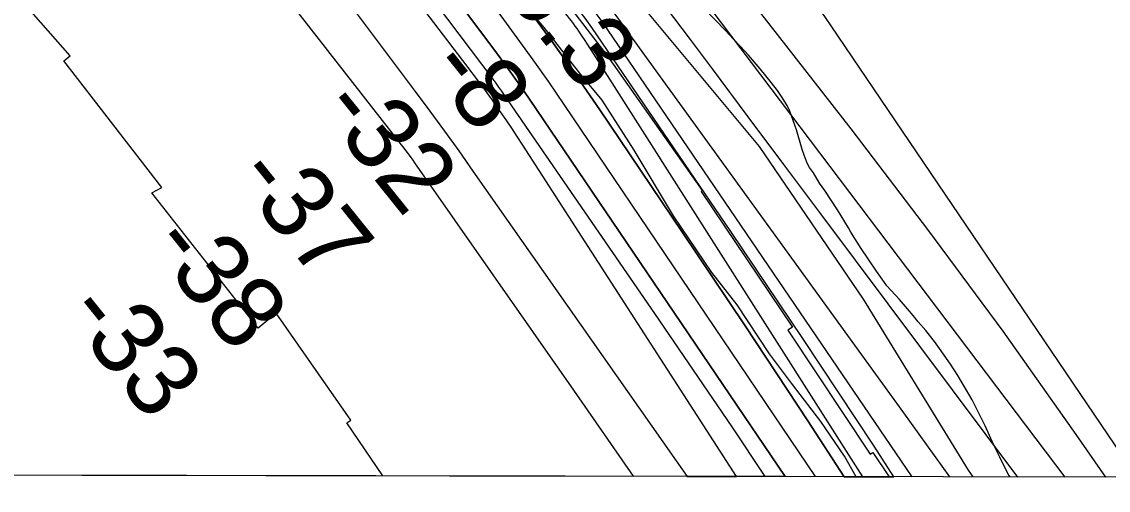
# Model space of a CAD drawing. Extents: x 3192986 to 3230865, y 867483 to 892886.
# Drawn here: x 3221191 to 3222187, y 872862 to 873292 of the extents above; entities that cross this region are included whole.
import ezdxf

# ---------------------------------------------------------------- set-up
doc = ezdxf.new("R2010")
doc.units = 0
for name, color, linetype in [('V-GRID-FRAM', 7, 'Continuous'), ('V-RIVR-EDGE', 7, 'Continuous'), ('V-RIVR-RANG', 7, 'Continuous'), ('V-RRAP-FSHR', 7, 'Continuous'), ('V-RRAP-RVMT', 7, 'Continuous'), ('V-SITE-VEGE', 7, 'Continuous'), ('V-TOPO-DPTH', 7, 'Continuous'), ('V-TOPO-MAJR', 7, 'Continuous'), ('V-TOPO-MINR', 7, 'Continuous'), ('V-TOPO-WATR', 7, 'Continuous')]:
    doc.layers.add(name, color=color, linetype=linetype)

msp = doc.modelspace()

# ---------------------------------------------------------------- linework, layer by layer
at = {"layer": 'V-GRID-FRAM'}
msp.add_lwpolyline([(3197228.98, 891108.84), (3228580.58, 891049.56), (3228554.13, 872861.57), (3197186.66, 872920.88)], dxfattribs=at)
at = {"layer": 'V-RIVR-EDGE'}
msp.add_lwpolyline([(3221955.99, 872874.04), (3221945.27, 872892.84), (3221923.62, 872924.62), (3221896.75, 872959.9), (3221876.39, 872986.9), (3221846.94, 873031.74), (3221823.54, 873061.36), (3221788.46, 873113.61), (3221752.53, 873173.68), (3221723.09, 873219.83), (3221703.59, 873243.35), (3221669.79, 873286.47), (3221630.35, 873332.64)], dxfattribs=at)
at = {"layer": 'V-RRAP-FSHR'}
msp.add_lwpolyline([(3221070.16, 874134.12), (3221108.41, 874083.35), (3221205.98, 873971.1), (3221288.17, 873882.52), (3221420.05, 873732.91), (3221529.87, 873601.58), (3221600.18, 873512.62), (3221703.9, 873384.12), (3221766.03, 873298.44), (3221867.11, 873177.32), (3221962.41, 873036.87), (3222058.75, 872880.07), (3222063.05, 872873.84)], dxfattribs=at)
at = {"layer": 'V-RRAP-RVMT'}
for p, q in [((3221632.79, 873384.49), (3221727.37, 873260.89)), ((3221235.06, 873260.39), (3221148.64, 873358.8)), ((3221229.29, 873255.72), (3221235.06, 873260.39)), ((3221319.18, 873139.67), (3221229.29, 873255.72)), ((3221727.37, 873260.89), (3221814.76, 873136.7)), ((3221309.86, 873134.5), (3221319.18, 873139.67)), ((3221407.46, 873010.38), (3221309.86, 873134.5)), ((3221814.76, 873136.7), (3221813.92, 873136)), ((3221813.92, 873136), (3221897.47, 873011.29)), ((3221423.89, 873024.32), (3221407.46, 873010.38)), ((3221492.37, 872925.87), (3221423.89, 873024.32)), ((3221897.47, 873011.29), (3221893.37, 873008.69)), ((3221893.37, 873008.69), (3221968.83, 872894.59)), ((3221488.73, 872923.41), (3221492.37, 872925.87)), ((3221521.8, 872874.86), (3221488.73, 872923.41)), ((3221968.83, 872894.59), (3221971.2, 872896.29)), ((3221971.2, 872896.29), (3221986.18, 872873.99)), ((3221986.18, 872873.99), (3221521.8, 872874.86))]:
    msp.add_line(p, q, dxfattribs=at)
at = {"layer": 'V-SITE-VEGE'}
for p, q in [((3221836.3, 873283.71), (3221816.47, 873303.91)), ((3221843.45, 873275.7), (3221836.3, 873283.71)), ((3221849.64, 873269.4), (3221843.45, 873275.7)), ((3221857.21, 873261.1), (3221849.64, 873269.4)), ((3221868.05, 873248.38), (3221857.21, 873261.1)), ((3221878.34, 873235.67), (3221868.05, 873248.38)), ((3221883.82, 873228.54), (3221878.34, 873235.67)), ((3221887.64, 873222.99), (3221883.82, 873228.54)), ((3221892.82, 873214.88), (3221887.64, 873222.99)), ((3221895.24, 873209.63), (3221892.82, 873214.88)), ((3221899.77, 873196.9), (3221895.24, 873209.63)), ((3221901.22, 873192.38), (3221899.77, 873196.9)), ((3221906.48, 873174.29), (3221901.22, 873192.38)), ((3221908.21, 873169.34), (3221906.48, 873174.29)), ((3221911.15, 873161.97), (3221908.21, 873169.34)), ((3221913.32, 873157.86), (3221911.15, 873161.97)), ((3221916.73, 873152.87), (3221913.32, 873157.86)), ((3221922.31, 873143.63), (3221916.73, 873152.87)), ((3221927.23, 873136.79), (3221922.31, 873143.63)), ((3221938.82, 873119.14), (3221927.23, 873136.79)), ((3221949.03, 873102.37), (3221938.82, 873119.14)), ((3221951.2, 873098.39), (3221949.03, 873102.37)), ((3221960.6, 873083.59), (3221951.2, 873098.39)), ((3221974.65, 873062.66), (3221960.6, 873083.59)), ((3221979.7, 873055.4), (3221974.65, 873062.66)), ((3221984.08, 873049.41), (3221979.7, 873055.4)), ((3221995.63, 873036.68), (3221984.08, 873049.41)), ((3222003.19, 873028.1), (3221995.63, 873036.68)), ((3222008.4, 873021.96), (3222003.19, 873028.1)), ((3222012.93, 873016.25), (3222008.4, 873021.96)), ((3222019.79, 873008.39), (3222012.93, 873016.25)), ((3222027.74, 872998.26), (3222019.79, 873008.39)), ((3222032.53, 872991.84), (3222027.74, 872998.26)), ((3222042.5, 872977.45), (3222032.53, 872991.84)), ((3222049.32, 872967.06), (3222042.5, 872977.45)), ((3222062.5, 872944.75), (3222049.32, 872967.06)), ((3222074.25, 872920.77), (3222062.5, 872944.75)), ((3222082.19, 872903.06), (3222074.25, 872920.77)), ((3222084.88, 872897.38), (3222082.19, 872903.06)), ((3222087.72, 872891.85), (3222084.88, 872897.38)), ((3222095.28, 872876.25), (3222087.72, 872891.85)), ((3222097.27, 872873.78), (3222095.28, 872876.25)), ((3224312.1, 872869.59), (3222097.27, 872873.78))]:
    msp.add_line(p, q, dxfattribs=at)
at = {"layer": 'V-TOPO-DPTH'}
for points in [[(3221944.84, 872874.06), (3221990.5, 872873.98), (3221972.5, 872901.96), (3221907.17, 873000.85), (3221841.03, 873099.22), (3221713.44, 873286.52), (3221710.43, 873290.8), (3221707.36, 873295.02), (3221704.16, 873299.16), (3221700.9, 873303.24), (3221568.24, 873464.46), (3221497.91, 873548.52), (3221426.69, 873631.8), (3221354.12, 873713.91), (3221280.65, 873795.25), (3221093.52, 873999.05), (3221074.16, 874019.8), (3221054.59, 874040.33), (3221034.68, 874060.54), (3221014.56, 874080.55), (3220391.6, 874689.89)], [(3220345.64, 874636.33), (3220668.14, 874354.93), (3220729.72, 874300.19), (3220790.61, 874244.7), (3220850.47, 874188.1), (3220909.63, 874130.76), (3221013.79, 874027.92), (3221020.28, 874021.37), (3221026.68, 874014.72), (3221032.92, 874007.93), (3221039.07, 874001.05), (3221154.89, 873868.49), (3221218.02, 873794.56), (3221280, 873719.7), (3221340.26, 873643.46), (3221399.38, 873566.29), (3221626.15, 873263.23), (3221633.89, 873252.72), (3221641.53, 873242.15), (3221649.02, 873231.47), (3221656.41, 873220.71), (3221890.92, 872874.17)], [(3221944.84, 872874.06), (3221890.92, 872874.17), (3221656.41, 873220.71), (3221649.02, 873231.47), (3221641.53, 873242.15), (3221633.89, 873252.72), (3221626.15, 873263.23), (3221399.38, 873566.29), (3221340.26, 873643.46), (3221280, 873719.7), (3221218.02, 873794.56), (3221154.89, 873868.49), (3221039.07, 874001.05), (3221032.92, 874007.93), (3221026.68, 874014.72), (3221020.28, 874021.37), (3221013.79, 874027.92), (3220909.63, 874130.76), (3220850.47, 874188.1), (3220790.61, 874244.7), (3220729.72, 874300.19), (3220668.14, 874354.93), (3220345.64, 874636.33)], [(3221751.62, 872874.43), (3221696.98, 872953.36), (3221551.33, 873162.21), (3221549.65, 873164.58), (3221547.95, 873166.93), (3221546.2, 873169.25), (3221544.43, 873171.56), (3221009.68, 873856.85), (3220998.83, 873870.57), (3220987.87, 873884.19), (3220976.73, 873897.67), (3220965.47, 873911.06), (3220945.52, 873934.47), (3220942.71, 873937.62), (3220939.76, 873940.62), (3220919.03, 873960.8), (3220907.08, 873972.27), (3220895.03, 873983.65), (3220882.83, 873994.86), (3220870.54, 874005.97), (3220246.45, 874562.68)], [(3221751.62, 872874.43), (3221696.98, 872953.36), (3221551.33, 873162.21), (3221549.65, 873164.58), (3221547.95, 873166.93), (3221546.2, 873169.25), (3221544.43, 873171.56), (3221009.68, 873856.85), (3220998.83, 873870.57), (3220987.87, 873884.19), (3220976.73, 873897.67), (3220965.47, 873911.06), (3220945.52, 873934.47), (3220942.71, 873937.62), (3220939.76, 873940.62), (3220919.03, 873960.8), (3220907.08, 873972.27), (3220895.03, 873983.65), (3220882.83, 873994.86), (3220870.54, 874005.97), (3220246.45, 874562.68)], [(3220597.51, 874457.45), (3220658.01, 874400.29), (3220717.73, 874342.29), (3221014.21, 874048.19), (3221025.85, 874036.42), (3221037.32, 874024.49), (3221048.55, 874012.33), (3221059.61, 874000.01), (3221463.82, 873540.94), (3221501.31, 873497.49), (3221538.19, 873453.54), (3221574.17, 873408.85), (3221609.55, 873363.66), (3221634.16, 873331.55), (3221656.5, 873301.85), (3221678.47, 873271.88), (3221699.88, 873241.51), (3221720.93, 873210.88), (3221796.07, 873099.26), (3221854.07, 873012.4), (3221911.62, 872925.24), (3221944.84, 872874.06)], [(3220597.51, 874457.45), (3220658.01, 874400.29), (3220717.73, 874342.29), (3221014.21, 874048.19), (3221025.85, 874036.42), (3221037.32, 874024.49), (3221048.55, 874012.33), (3221059.61, 874000.01), (3221463.82, 873540.94), (3221501.31, 873497.49), (3221538.19, 873453.54), (3221574.17, 873408.85), (3221609.55, 873363.66), (3221634.16, 873331.55), (3221656.5, 873301.85), (3221678.47, 873271.88), (3221699.88, 873241.51), (3221720.93, 873210.88), (3221796.07, 873099.26), (3221854.07, 873012.4), (3221911.62, 872925.24), (3221944.84, 872874.06)], [(3220592.45, 874313.38), (3220671.23, 874240.56), (3220749.06, 874166.7), (3220940.29, 873981.66), (3220952.37, 873969.62), (3220964.2, 873957.34), (3220975.66, 873944.72), (3220986.88, 873931.86), (3221167.69, 873718.18), (3221238.86, 873632.55), (3221308.99, 873546.09), (3221377.57, 873458.39), (3221445.11, 873369.87), (3221551.6, 873227.69), (3221565.03, 873209.57), (3221578.35, 873191.38), (3221591.49, 873173.06), (3221604.52, 873154.66), (3221800.98, 872874.34), (3221846.32, 872874.25)], [(3220592.45, 874313.38), (3220671.23, 874240.56), (3220749.06, 874166.7), (3220940.29, 873981.66), (3220952.37, 873969.62), (3220964.2, 873957.34), (3220975.66, 873944.72), (3220986.88, 873931.86), (3221167.69, 873718.18), (3221238.86, 873632.55), (3221308.99, 873546.09), (3221377.57, 873458.39), (3221445.11, 873369.87), (3221551.6, 873227.69), (3221565.03, 873209.57), (3221578.35, 873191.38), (3221591.49, 873173.06), (3221604.52, 873154.66), (3221800.98, 872874.34), (3221751.62, 872874.43)], [(3221890.92, 872874.17), (3221846.32, 872874.25), (3221650.2, 873178.51), (3221645.18, 873186.21), (3221640.1, 873193.89), (3221634.95, 873201.51), (3221629.74, 873209.1), (3221625.56, 873215.12), (3221622.38, 873219.66), (3221619.17, 873224.17), (3221615.93, 873228.65), (3221612.65, 873233.1), (3221609.34, 873237.54), (3221606.02, 873241.97), (3221602.68, 873246.38), (3221599.34, 873250.79), (3221555.84, 873307.92), (3221530.72, 873340.87), (3221505.58, 873373.81), (3221480.41, 873406.73), (3221455.23, 873439.63), (3221088.35, 873918.36)], [(3221846.32, 872874.25), (3221650.2, 873178.51), (3221645.18, 873186.21), (3221640.1, 873193.89), (3221634.95, 873201.51), (3221629.74, 873209.1), (3221625.56, 873215.12), (3221622.38, 873219.66), (3221619.17, 873224.17), (3221615.93, 873228.65), (3221612.65, 873233.1), (3221609.34, 873237.54), (3221606.02, 873241.97), (3221602.68, 873246.38), (3221599.34, 873250.79), (3221555.84, 873307.92), (3221530.72, 873340.87), (3221505.58, 873373.81), (3221480.41, 873406.73), (3221455.23, 873439.63), (3221088.35, 873918.36)], [(3220453.98, 873461), (3220706.94, 873216.97), (3220775.93, 873151.12), (3220845.38, 873085.76), (3220915.52, 873021.14), (3220986.11, 872957.01), (3221076.58, 872875.71), (3221751.62, 872874.43)]]:
    msp.add_lwpolyline(points, dxfattribs=at)
at = {"layer": 'V-TOPO-MAJR'}
msp.add_lwpolyline([(3222104.27, 872873.76), (3221955.41, 873072.78), (3221922.59, 873116.67), (3221889.77, 873160.56), (3221856.95, 873204.44), (3221824.13, 873248.33), (3221803.91, 873275.38), (3221781.05, 873305.62), (3221757.98, 873335.7), (3221734.59, 873365.54), (3221711, 873395.22), (3221672.96, 873442.56), (3221629.74, 873495.41), (3221585.94, 873547.76), (3221541.25, 873599.36), (3221495.98, 873650.45), (3221119.03, 874068.6), (3221111.33, 874076.99), (3221103.53, 874085.29)], dxfattribs=at)
at = {"layer": 'V-TOPO-MINR'}
for points in [[(3222041.76, 872873.88), (3221999.77, 872932.76), (3221746.99, 873282.2), (3221736.66, 873296.23), (3221726.18, 873310.15), (3221715.46, 873323.89), (3221704.59, 873337.51), (3221302.56, 873832.79), (3221268.53, 873874.02), (3221234.07, 873914.88), (3221198.96, 873955.18), (3221163.4, 873995.1), (3221095.89, 874069.7), (3221093.75, 874072.02), (3221091.58, 874074.33), (3221089.38, 874076.59), (3221087.16, 874078.84), (3221049.6, 874116.1), (3221028.47, 874136.85), (3221007.22, 874157.47), (3220985.78, 874177.89), (3220964.2, 874198.18), (3220416.8, 874708)], [(3222007.35, 872873.95), (3221728.21, 873284.31), (3221722.05, 873293.09), (3221715.73, 873301.76), (3221709.16, 873310.24), (3221702.43, 873318.6), (3221267.96, 873843.37), (3221236.86, 873880.26), (3221205.33, 873916.76), (3221173.15, 873952.7), (3221140.53, 873988.25), (3221131.49, 873997.94), (3221102.89, 874028.19), (3221074.06, 874058.21), (3221044.87, 874087.88), (3221015.44, 874117.32), (3220954.94, 874177.12), (3220894.84, 874236.04), (3220834.42, 874294.63), (3220773.52, 874352.71), (3220712.29, 874410.46), (3220394.92, 874707.35)], [(3222184.84, 872873.61), (3222157.85, 872912.84), (3222090.76, 873007.55), (3222021.75, 873100.86), (3221951.45, 873193.25), (3221833.82, 873344.63), (3221821.26, 873360.54), (3221808.55, 873376.32), (3221795.61, 873391.91), (3221782.51, 873407.37), (3221260.49, 874014.29), (3221243.05, 874034.13), (3221225.32, 874053.71), (3221207.18, 874072.91), (3221188.75, 874091.84), (3221169.97, 874110.43), (3221151, 874128.82), (3221131.74, 874146.91), (3221112.3, 874164.8), (3220521.1, 874700.2)], [(3221990.5, 872873.98), (3221972.5, 872901.96), (3221907.17, 873000.85), (3221841.03, 873099.22), (3221713.44, 873286.52), (3221710.43, 873290.8), (3221707.36, 873295.02), (3221704.16, 873299.16), (3221700.9, 873303.24), (3221568.24, 873464.46), (3221497.91, 873548.52), (3221426.69, 873631.8), (3221354.12, 873713.91), (3221280.65, 873795.25), (3221093.52, 873999.05), (3221074.16, 874019.8), (3221054.59, 874040.33), (3221034.68, 874060.54), (3221014.56, 874080.55), (3220391.6, 874689.89)], [(3221872.68, 872874.2), (3221842.16, 872919.68), (3221771.27, 873023.89), (3221633.59, 873224.2), (3221631.01, 873227.9), (3221628.39, 873231.57), (3221625.73, 873235.22), (3221623.04, 873238.84), (3221238.54, 873748.66), (3221203.97, 873793.51), (3221168.78, 873837.86), (3221132.66, 873881.46), (3221095.93, 873924.55), (3221028.83, 874001.6), (3221025.13, 874005.76), (3221021.37, 874009.85), (3221017.52, 874013.86), (3221013.6, 874017.81), (3220952.09, 874078.4), (3220917.08, 874112.3), (3220881.68, 874145.77), (3220845.69, 874178.61), (3220809.32, 874211.04), (3220324.88, 874635.38)], [(3221890.92, 872874.17), (3221656.41, 873220.71), (3221649.02, 873231.47), (3221641.53, 873242.15), (3221633.89, 873252.72), (3221626.15, 873263.23), (3221399.38, 873566.29), (3221340.26, 873643.46), (3221280, 873719.7), (3221218.02, 873794.56), (3221154.89, 873868.49), (3221039.07, 874001.05), (3221032.92, 874007.93), (3221026.68, 874014.72), (3221020.28, 874021.37), (3221013.79, 874027.92), (3220909.63, 874130.76), (3220850.47, 874188.1), (3220790.61, 874244.7), (3220729.72, 874300.19), (3220668.14, 874354.93), (3220345.64, 874636.33)], [(3221751.62, 872874.43), (3221696.98, 872953.36), (3221551.33, 873162.21), (3221549.65, 873164.58), (3221547.95, 873166.93), (3221546.2, 873169.25), (3221544.43, 873171.56), (3221009.68, 873856.85), (3220998.83, 873870.57), (3220987.87, 873884.19), (3220976.73, 873897.67), (3220965.47, 873911.06), (3220945.52, 873934.47), (3220942.71, 873937.62), (3220939.76, 873940.62), (3220919.03, 873960.8), (3220907.08, 873972.27), (3220895.03, 873983.65), (3220882.83, 873994.86), (3220870.54, 874005.97), (3220246.45, 874562.68)], [(3222147.61, 872873.68), (3221787.97, 873349.93), (3221785.63, 873352.98), (3221783.27, 873356.01), (3221780.86, 873359.01), (3221778.43, 873361.99), (3221692.21, 873466.05), (3221646.23, 873520.68), (3221599.7, 873574.82), (3221552.33, 873628.24), (3221504.41, 873681.17), (3221149.21, 874067.48), (3221134.17, 874083.54), (3221118.94, 874099.42), (3221103.43, 874115.02), (3221087.73, 874130.44), (3220758.18, 874448.32), (3220703.21, 874500.63), (3220647.78, 874552.45)], [(3221962.19, 872874.03), (3221715.04, 873262.69), (3221712.33, 873266.92), (3221709.6, 873271.14), (3221706.83, 873275.33), (3221704.04, 873279.51), (3221701.69, 873283), (3221700.04, 873285.41), (3221698.36, 873287.79), (3221696.62, 873290.13), (3221694.85, 873292.45), (3221693.04, 873294.74), (3221691.2, 873297), (3221689.32, 873299.23), (3221687.41, 873301.43), (3221069.93, 873999.53), (3221056.38, 874014.55), (3221042.65, 874029.39), (3221028.64, 874043.96), (3221014.44, 874058.35), (3220559.09, 874511.17)], [(3221918.67, 872874.11), (3221688.28, 873215.85), (3221674.15, 873236.44), (3221659.81, 873256.86), (3221645.14, 873277.05), (3221630.25, 873297.08), (3221532.68, 873426.09), (3221467.95, 873509.78), (3221402.03, 873592.5), (3221334.33, 873673.77), (3221265.44, 873754.08), (3221049.33, 874000.52), (3221040.73, 874010.12), (3221031.99, 874019.6), (3221023.06, 874028.89), (3221013.99, 874038.05), (3220865.22, 874185.27), (3220780.89, 874267.11), (3220695.52, 874347.82), (3220608.58, 874426.85)], [(3220592.45, 874313.38), (3220671.23, 874240.56), (3220749.06, 874166.7), (3220940.29, 873981.66), (3220952.37, 873969.62), (3220964.2, 873957.34), (3220975.66, 873944.72), (3220986.88, 873931.86), (3221167.69, 873718.18), (3221238.86, 873632.55), (3221308.99, 873546.09), (3221377.57, 873458.39), (3221445.11, 873369.87), (3221551.6, 873227.69), (3221565.03, 873209.57), (3221578.35, 873191.38), (3221591.49, 873173.06), (3221604.52, 873154.66), (3221800.98, 872874.34)], [(3222213.29, 872873.56), (3221933.07, 873288.08), (3221919.16, 873308.24), (3221905, 873328.21), (3221890.46, 873347.9), (3221875.65, 873367.41), (3221860.55, 873386.69), (3221845.3, 873405.84), (3221829.82, 873424.82), (3221814.2, 873443.68), (3221786.68, 873476.5), (3221757.08, 873511.58), (3221727.34, 873546.54), (3221697.37, 873581.31), (3221667.27, 873615.96), (3221213.55, 874134.84)], [(3221846.32, 872874.25), (3221650.2, 873178.51), (3221645.18, 873186.21), (3221640.1, 873193.89), (3221634.95, 873201.51), (3221629.74, 873209.1), (3221625.56, 873215.12), (3221622.38, 873219.66), (3221619.17, 873224.17), (3221615.93, 873228.65), (3221612.65, 873233.1), (3221609.34, 873237.54), (3221606.02, 873241.97), (3221602.68, 873246.38), (3221599.34, 873250.79), (3221555.84, 873307.92), (3221530.72, 873340.87), (3221505.58, 873373.81), (3221480.41, 873406.73), (3221455.23, 873439.63), (3221088.35, 873918.36)]]:
    msp.add_lwpolyline(points, dxfattribs=at)
at = {"layer": 'V-TOPO-WATR'}
msp.add_lwpolyline([(3221944.84, 872874.06), (3221911.62, 872925.24), (3221854.07, 873012.4), (3221796.07, 873099.26), (3221720.93, 873210.88), (3221699.88, 873241.51), (3221678.47, 873271.88), (3221656.5, 873301.85), (3221634.16, 873331.55), (3221609.55, 873363.66), (3221574.17, 873408.85), (3221538.19, 873453.54), (3221501.31, 873497.49), (3221463.82, 873540.94), (3221059.61, 874000.01), (3221048.55, 874012.33), (3221037.32, 874024.49), (3221025.85, 874036.42), (3221014.21, 874048.19), (3220717.73, 874342.29), (3220658.01, 874400.29), (3220597.51, 874457.45)], dxfattribs=at)

# ---------------------------------------------------------------- texts
at = {"layer": 'V-RIVR-RANG'}
for s, p in [('16.3', (3221598.94, 873360.18)), ('-8', (3221560.63, 873248.19)), ('-32', (3221461.86, 873211.46)), ('-37', (3221383.91, 873148.83)), ('-38', (3221305.95, 873086.19)), ('-33', (3221228, 873023.56))]:
    msp.add_text(s, height=67, rotation=308.77361, dxfattribs=at).set_placement(p)

doc.saveas('drawing.dxf')
